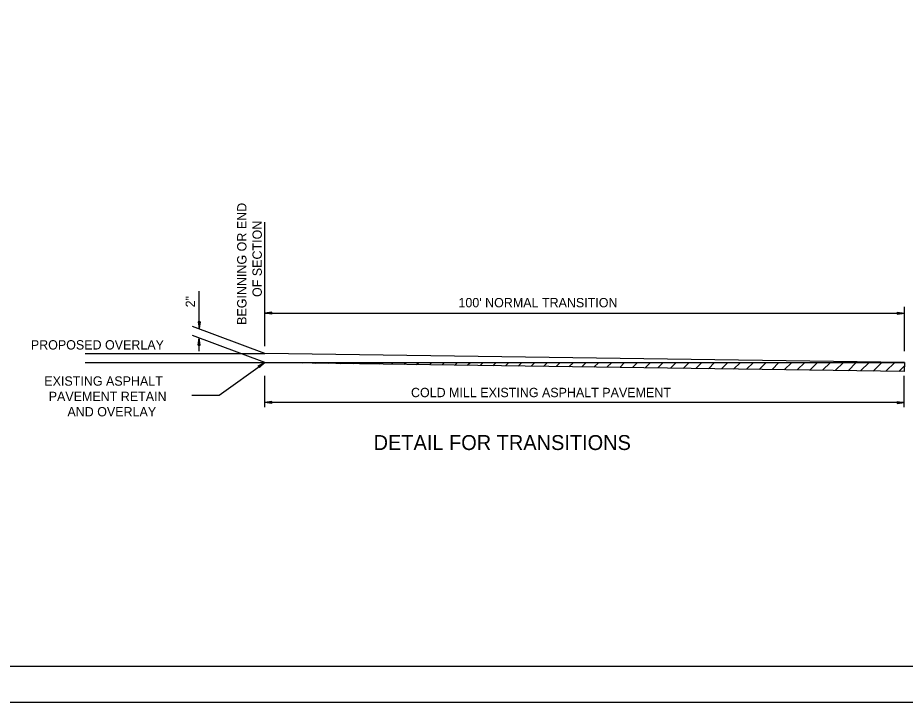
# Model space of a CAD drawing. Extents: x 438659 to 573674, y 10724 to 98600.
# Drawn here: x 448722 to 465846, y 52630 to 65830 of the extents above; entities that cross this region are included whole.
import ezdxf

# ---------------------------------------------------------------- set-up
doc = ezdxf.new("R2010")
doc.units = 0
for name, color, linetype in [('border', 7, 'Continuous'), ('Default', 7, 'Continuous'), ('R_Striping', 7, 'Continuous')]:
    doc.layers.add(name, color=color, linetype=linetype)

msp = doc.modelspace()

# ---------------------------------------------------------------- linework, layer by layer
at = {"layer": 'Default'}
for p, q in [((453487, 59495), (453487, 61891)), ((452221, 59835), (452221, 60555)), ((453627, 60155), (453487, 60135)), ((453487, 60135), (465833, 60135)), ((453627, 60115), (453487, 60135)), ((453627, 60148), (453507, 60135)), ((453627, 60115), (453507, 60135)), ((453627, 60148), (453534, 60135)), ((453627, 60121), (453534, 60135)), ((453627, 60141), (453560, 60135)), ((453627, 60121), (453560, 60135)), ((453627, 60141), (453580, 60135)), ((453627, 60128), (453580, 60135)), ((453627, 60135), (453607, 60135)), ((453627, 60128), (453607, 60135)), ((453627, 60115), (453627, 60155)), ((465693, 60155), (465833, 60135)), ((465693, 60155), (465693, 60115)), ((465693, 60148), (465787, 60135)), ((465693, 60148), (465806, 60135)), ((465693, 60141), (465740, 60135)), ((465693, 60141), (465760, 60135)), ((465693, 60115), (465833, 60135)), ((465693, 60128), (465740, 60135)), ((465693, 60121), (465787, 60135)), ((465693, 60115), (465806, 60135)), ((465693, 60121), (465760, 60135)), ((465693, 60128), (465713, 60135)), ((465693, 60135), (465713, 60135)), ((465833, 59402), (465833, 60254)), ((452201, 59968), (452221, 59835)), ((452201, 59968), (452221, 59855)), ((452241, 59968), (452201, 59968)), ((452208, 59968), (452221, 59882)), ((452208, 59968), (452221, 59901)), ((452214, 59968), (452221, 59928)), ((452214, 59968), (452221, 59948)), ((452241, 59968), (452221, 59835)), ((452227, 59968), (452221, 59928)), ((452234, 59968), (452221, 59882)), ((452234, 59968), (452221, 59855)), ((452227, 59968), (452221, 59901)), ((452221, 59968), (452221, 59948)), ((453487, 59355), (452094, 59875)), ((453487, 59182), (452094, 59702)), ((452201, 59515), (452221, 59655)), ((452201, 59515), (452221, 59635)), ((452208, 59515), (452221, 59608)), ((452241, 59515), (452221, 59655)), ((452221, 59402), (452221, 59655)), ((452234, 59515), (452221, 59635)), ((452234, 59515), (452221, 59608)), ((452201, 59515), (452241, 59515)), ((452208, 59515), (452221, 59589)), ((452214, 59515), (452221, 59562)), ((452214, 59515), (452221, 59535)), ((452227, 59515), (452221, 59589)), ((452227, 59515), (452221, 59562)), ((452221, 59515), (452221, 59535)), ((450022, 59355), (453487, 59355)), ((465833, 59182), (453487, 59355)), ((450022, 59182), (465833, 59182)), ((452608, 58549), (453487, 59182)), ((453360, 59115), (453487, 59182)), ((453360, 59115), (453387, 59082)), ((453367, 59115), (453467, 59169)), ((453367, 59115), (453447, 59155)), ((453367, 59109), (453427, 59142)), ((453367, 59109), (453414, 59129)), ((453374, 59102), (453393, 59115)), ((453374, 59102), (453393, 59115)), ((453380, 59089), (453447, 59155)), ((453380, 59095), (453427, 59142)), ((453380, 59095), (453414, 59129)), ((453387, 59082), (453487, 59182)), ((453387, 59089), (453467, 59169)), ((465826, 59008), (453487, 59182)), ((453973, 59175), (453980, 59182)), ((454216, 59172), (454226, 59182)), ((454459, 59168), (454479, 59182)), ((454709, 59165), (454726, 59182)), ((454952, 59161), (454973, 59182)), ((455195, 59158), (455219, 59182)), ((455439, 59155), (455466, 59182)), ((455688, 59151), (455719, 59182)), ((455931, 59148), (455966, 59182)), ((456181, 59144), (456212, 59182)), ((456418, 59141), (456459, 59182)), ((456667, 59137), (456712, 59182)), ((456910, 59134), (456959, 59182)), ((457159, 59130), (457205, 59182)), ((457396, 59127), (457458, 59182)), ((457646, 59124), (457705, 59182)), ((457890, 59120), (457951, 59182)), ((458133, 59116), (458198, 59182)), ((458376, 59113), (458451, 59182)), ((458625, 59110), (458697, 59182)), ((458868, 59106), (458944, 59182)), ((459111, 59103), (459190, 59182)), ((459354, 59100), (459443, 59182)), ((459604, 59096), (459690, 59182)), ((459840, 59093), (459936, 59182)), ((460090, 59089), (460183, 59182)), ((460340, 59086), (460430, 59182)), ((460583, 59082), (460683, 59182)), ((460826, 59079), (460929, 59182)), ((461070, 59076), (461176, 59182)), ((461319, 59072), (461429, 59182)), ((461563, 59069), (461676, 59182)), ((461806, 59065), (461922, 59182)), ((462048, 59062), (462168, 59182)), ((462298, 59058), (462422, 59182)), ((462535, 59055), (462668, 59182)), ((462784, 59051), (462915, 59182)), ((463028, 59048), (463161, 59182)), ((463277, 59044), (463408, 59182)), ((463513, 59041), (463661, 59182)), ((463763, 59038), (463908, 59182)), ((464008, 59035), (464154, 59182)), ((464250, 59031), (464401, 59182)), ((464493, 59027), (464654, 59182)), ((464742, 59024), (464900, 59182)), ((464985, 59020), (465147, 59182)), ((465229, 59017), (465393, 59182)), ((465472, 59014), (465647, 59182)), ((465721, 59010), (465831, 59119)), ((465833, 59182), (465826, 59008)), ((453487, 58322), (453487, 58922)), ((465826, 58322), (465826, 58922)), ((452081, 58549), (452608, 58549)), ((453621, 58429), (453487, 58409)), ((453621, 58429), (453487, 58409)), ((465826, 58409), (453487, 58409)), ((453621, 58389), (453487, 58409)), ((453621, 58389), (453487, 58409)), ((453621, 58429), (453507, 58409)), ((453621, 58429), (453507, 58409)), ((453621, 58396), (453507, 58409)), ((453621, 58396), (453507, 58409)), ((453621, 58423), (453534, 58409)), ((453621, 58423), (453534, 58409)), ((453621, 58396), (453534, 58409)), ((453621, 58396), (453534, 58409)), ((453621, 58423), (453553, 58409)), ((453621, 58423), (453553, 58409)), ((453621, 58402), (453553, 58409)), ((453621, 58402), (453553, 58409)), ((453621, 58415), (453580, 58409)), ((453621, 58415), (453580, 58409)), ((453621, 58402), (453580, 58409)), ((453621, 58402), (453580, 58409)), ((453621, 58415), (453600, 58409)), ((453621, 58415), (453600, 58409)), ((453621, 58409), (453600, 58409)), ((453621, 58409), (453600, 58409)), ((453621, 58389), (453621, 58429)), ((453621, 58389), (453621, 58429)), ((465693, 58429), (465826, 58409)), ((465693, 58429), (465806, 58409)), ((465693, 58429), (465693, 58389)), ((465693, 58423), (465780, 58409)), ((465693, 58423), (465760, 58409)), ((465693, 58415), (465733, 58409)), ((465693, 58415), (465713, 58409)), ((465693, 58389), (465826, 58409)), ((465693, 58402), (465733, 58409)), ((465693, 58396), (465780, 58409)), ((465693, 58396), (465806, 58409)), ((465693, 58402), (465760, 58409)), ((465693, 58409), (465713, 58409))]:
    msp.add_line(p, q, dxfattribs=at)
at = {"layer": 'R_Striping'}
msp.add_line((478767, 53322), (440478, 53322), dxfattribs=at)
for points in [[(479459, 79030), (438659, 79030), (438659, 52630), (479459, 52630)], [(440478, 53322), (440478, 78338), (468896, 78338), (468896, 77152), (473595, 77152), (473595, 76802), (478767, 76802), (478767, 53322)]]:
    msp.add_lwpolyline(points, close=True, dxfattribs=at)

# ---------------------------------------------------------------- texts
at = {"layer": 'border'}
msp.add_text('DETAIL FOR TRANSITIONS', height=288, dxfattribs=at).set_placement((455588, 57494))
at = {"layer": 'Default'}
for s, p in [('BEGINNING OR END', (453135, 59907)), ('OF SECTION', (453431, 60445)), ('2"', (452141, 60245))]:
    msp.add_text(s, height=180, rotation=90, dxfattribs=at).set_placement(p)
for s, p in [("100' NORMAL TRANSITION", (457225, 60246)), ('PROPOSED OVERLAY', (448974, 59432)), ('EXISTING ASPHALT', (449234, 58734)), ('PAVEMENT RETAIN', (449319, 58438)), ('COLD MILL EXISTING ASPHALT PAVEMENT', (456309, 58513)), ('AND OVERLAY', (449680, 58142))]:
    msp.add_text(s, height=180, dxfattribs=at).set_placement(p)

doc.saveas('drawing.dxf')
